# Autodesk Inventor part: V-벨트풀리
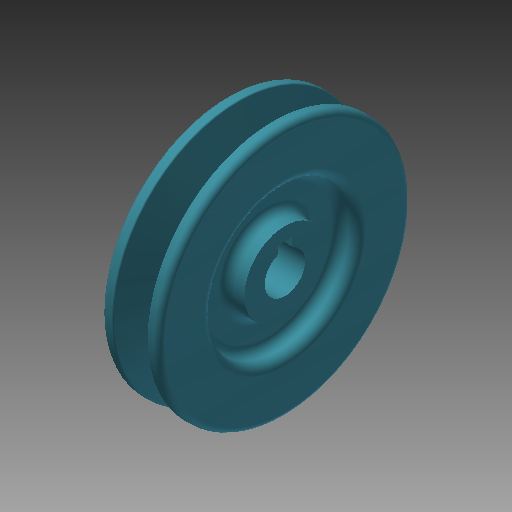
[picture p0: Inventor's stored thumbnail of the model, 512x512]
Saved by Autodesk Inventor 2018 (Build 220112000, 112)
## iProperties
Created: 2019-09
Part Number: V-벨트풀리
Material: 알루미늄 6061
Document SubType Name: Modeling
Designer: mduedu
Density: 2.71 g/cm^3
Appearance: 커뎃 파란색
Mass: 202.902 g
Surface Area: 230.066 cm^2
Volume: 74.8717 cm^3
Author: mduedu
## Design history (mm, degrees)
sketch "스케치1"
  geometry: L1 (-10, 0)-(10, 0); L2 (10, 0)-(10, 43.5); L3 (10, 43.5)-(-10, 43.5); L4 (-10, 43.5)-(-10, 0); L5 (0, 0)-(0, 43.5); L6 (-5.976, 43.5)-(-2.154, 31); L7 (-2.154, 31)-(2.154, 31); L8 (2.154, 31)-(5.976, 43.5); L9 (-10, 39)-(10, 39); 3 further points
  constraints: 18 end point, 8 point on line, 3 perpendicular, 2 midpoint, 2 parallel, 1 coincident, 1 horizontal, 1 other
  dimensions: "d0" = 87 diameter of L3 L1; "d3" = 12.5 distance between parallel lines of L7 L3; "d4" = 34 deg angle of L8 L6; "d5" = 20 distance between parallel lines of L2 L4; "d6" = 8 distance between parallel lines of L9 L7; "d7" = 9.2 distance of point (4.6, 39) point (-4.6, 39)
revolve "회전1" sketch "스케치1" stored, may be unused: angle "d8" = 90 deg
sketch "스케치2"
  geometry: C1 r 14 at (0, 0); C2 r 25 at (0, 0); 1 further point
  constraints: 2 centre point, 2 coincident
  dimensions: "d9" = 28 diameter of C1; "d10" = 50 diameter of C2
extrude "돌출1" cut sketch "스케치2" distance "d11" = 6; taper "d12" = 0 deg
fillet "모깎기1" dims "d13" = 3
fillet "모깎기2" dims "d14" = 3
fillet "모깎기3" dims "d15" = 0.5, "d16" = 1, "d17" = 2
sketch "스케치3"
  geometry: L1 (-2.5, 6.538)-(2.5, 6.538); L2 (2.5, 6.538)-(2.5, 9.3); L3 (2.5, 9.3)-(-2.5, 9.3); L4 (-2.5, 9.3)-(-2.5, 6.538); A1 r 7 centre (0, 0) between (-2.5, 6.538) and (2.5, 6.538); 1 further point
  constraints: 8 end point, 2 parallel, 2 point on circle, 1 centre point, 1 coincident, 1 horizontal, 1 perpendicular
  dimensions: "d18" = 14 diameter of A1; "d20" = 5 distance of L2.end L3.end; "d21" = 16.3 dimension on A1 L3
extrude "돌출2" cut sketch "스케치3" extent not by distance; stored distance "d22" = 6; taper "d23" = 0 deg
node "솔리드1"
mirror "대칭1"
